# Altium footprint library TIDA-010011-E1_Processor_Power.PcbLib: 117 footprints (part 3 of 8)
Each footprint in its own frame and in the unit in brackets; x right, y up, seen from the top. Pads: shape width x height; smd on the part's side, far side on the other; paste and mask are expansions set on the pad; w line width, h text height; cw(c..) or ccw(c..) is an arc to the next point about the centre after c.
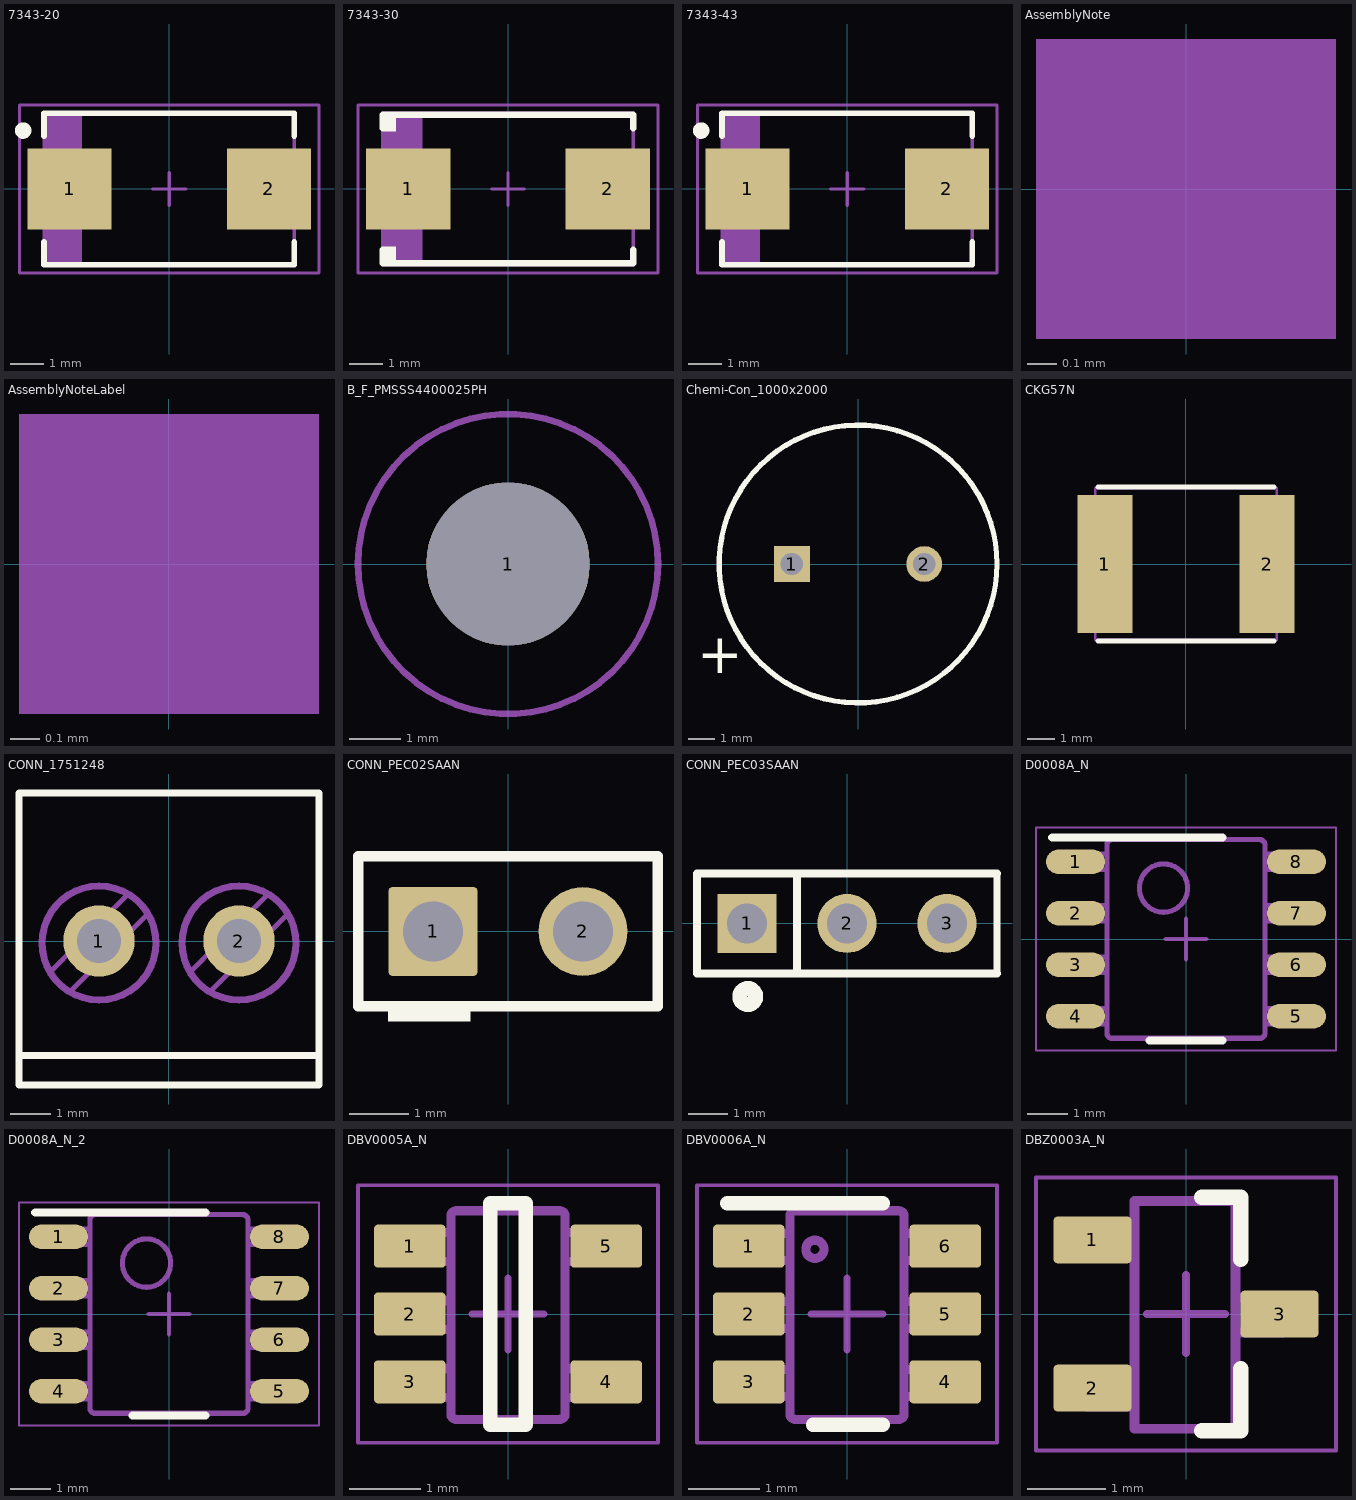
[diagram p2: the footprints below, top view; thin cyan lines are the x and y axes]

## 7343-20 [mm] "Medium density IPC, based on Kemet case V from T495 datasheet"
height 2
pads (2):
  rect 2.55x2.45 smd: 1(-3.025,0) 2(3.025,0)
Top Overlay:
  circle w0.25: c-4.439,1.775 r0.125
  lines w0.178: -3.8,-1.614 -3.8,-2.3 3.8,-2.3 3.8,-1.614 ; -3.8,1.614 -3.8,2.3 3.8,2.3 3.8,1.614
Mechanical 5:
  rectangle: -3.8,-2.3 -2.7,2.3
  lines w0.1: -2.7,-2.3 -2.7,2.3 ; -3.8,-2.3 3.8,-2.3 3.8,2.3 -3.8,2.3 -3.8,-2.3
  text ".Designator" at 0.343,-0.806 h0.51
Mechanical 15:
  lines w0.1: -0.5,0 0.5,0 ; 0,-0.5 0,0.5 ; -4.55,-2.55 -4.55,2.55 4.55,2.55 4.55,-2.55 -4.55,-2.55
3D body: height 2, standoff 0, extent -3.8,-2.3 3.8,2.3
3D body: height 2, standoff 2, extent -3.799,-2.299 -2.701,2.299

## 7343-30 [mm] "Medium Density based on Kemet T495 dimensions"
height 3
pads (2):
  rect 2.55x2.45 smd: 1(-3.025,0) 2(3.025,0)
Top Overlay:
  rectangle: -3.8,1.75 -3.4,2.25
  rectangle: -3.8,-2.25 -3.4,-1.75
  lines w0.2: -3.8,-1.85 -3.8,-2.25 3.8,-2.25 3.8,-1.85 ; -3.8,1.85 -3.8,2.25 3.8,2.25 3.8,1.85
Mechanical 5:
  rectangle: -3.8,-2.3 -2.65,2.3
  lines w0.1: -2.65,-2.3 -2.65,2.3 ; -3.8,-2.3 3.8,-2.3 3.8,2.3 -3.8,2.3 -3.8,-2.3
  text ".Designator" at 0.038,0.679 h0.51
Mechanical 15:
  lines w0.1: -0.5,0 0.5,0 ; 0,-0.5 0,0.5 ; -4.55,-2.55 -4.55,2.55 4.55,2.55 4.55,-2.55 -4.55,-2.55
3D body: height 3, standoff 0, extent -3.8,-2.3 3.8,2.3
3D body: height 3.1, standoff 3.01, extent -3.799,-2.299 -2.651,2.299

## 7343-43 [mm] "Medium density IPC based on Kemet T495 series"
height 4.3
pads (2):
  rect 2.55x2.45 smd: 1(-3.025,0) 2(3.025,0)
Top Overlay:
  circle w0.25: c-4.439,1.775 r0.125
  lines w0.178: -3.8,-1.614 -3.8,-2.3 3.8,-2.3 3.8,-1.614 ; -3.8,1.614 -3.8,2.3 3.8,2.3 3.8,1.614
Mechanical 5:
  rectangle: -3.8,-2.3 -2.7,2.3
  lines w0.1: -2.7,-2.3 -2.7,2.3 ; -3.8,-2.3 3.8,-2.3 3.8,2.3 -3.8,2.3 -3.8,-2.3
  text ".Designator" at 0.404,-0.45 h0.51
Mechanical 15:
  lines w0.1: -0.5,0 0.5,0 ; 0,-0.5 0,0.5 ; -4.55,-2.55 4.55,-2.55 4.55,2.55 -4.55,2.55 -4.55,-2.55
3D body: height 4.3, standoff 0, extent -3.8,-2.3 3.8,2.3
3D body: height 4.3, standoff 4.3, extent -3.799,-2.299 -2.701,2.299

## AssemblyNote [mm] "Assembly Note"
Mechanical 5:
  rectangle: -0.508,-0.508 0.508,0.508
  text ".Comment" at 1.143,-0.508 h0.51
  text ".Designator" at -4.191,-0.508 h0.51

## AssemblyNoteLabel [mm] "Assembly Note for PCB Labels"
Mechanical 5:
  rectangle: -0.508,-0.508 0.508,0.508
  text "Install label in silkscreened box after final wash.  Text shall be 8 pt font.  Text shall be per the Label Table in the PDF schematic." at 1.143,-0.508 h0.51
  text ".Designator" at -4.191,-0.508 h0.51

## B_F_PMSSS4400025PH [mm] "MACHINE SCREW PAN PHILLIPS 4-40"
height 2.1
pads (1):
  round 3.175 hole 3.175 unplated mask+0.127: 1(0,0)
Mechanical 5:
  circle w0.127: c0,0 r2.921
  text ".Designator" at -0.546,-0.121 h0.51
3D body "PMSSS 440 0025 PH.stp": height 2.01, standoff -6.3, extent -2.781,-2.781 2.781,2.781

## Chemi-Con_1000x2000 [mm] "TH, 2-Leads, Body 10x20mm, Pin Spacing 5mm"
height 21.5
pads (2):
  rect 1.35x1.35 hole 0.85: 1(-2.5,0)
  round 1.35 hole 0.85: 2(2.5,0)
Top Overlay:
  circle w0.2: c0,0 r5.25
  text "+" at -6.088,-4.128 h1.5
Mechanical 5:
  lines w0.1: 5.25,-0.001 cw(c0,0) 5.25,0
  text ".Designator" at -0.265,-1.143 h0.51
  text "+" at -3.897,-0.229 h0.51
3D body: height 0, standoff -2, extent 2.203,-0.299 2.8,0.3
3D body: height 0, standoff -2.5, extent -2.797,-0.299 -2.2,0.3
3D body: height 21.5, standoff 0, extent -4.25,-4.25 4.249,4.249
3D body: height 21.5, standoff 0, extent 3.68,-2.626 5.25,2.622
3D body: height 21.5, standoff 0, extent -5.249,-5.25 4.55,5.25

## CKG57N [mm] "Chip Capacitor, Body 6.0x5.0x5.0mm,"
height 5.5
pads (2):
  rect 2x5 smd: 1(-2.95,0) 2(2.95,0)
Top Overlay:
  lines w0.18: -3.2,-2.8 3.2,-2.8 ; -3.2,2.8 3.2,2.8
Mechanical 5:
  lines w0.1: -3.3,-2.75 3.3,-2.75 3.3,2.75 -3.3,2.75 -3.3,-2.75
  text ".Designator" at 0.227,-0.628 h0.51
3D body: height 1, standoff 0, extent 3.101,-2.749 3.299,2.749
3D body: height 1, standoff 0, extent -3.299,-2.749 -3.101,2.749
3D body: height 5.5, standoff 1, extent -2.199,-2.749 2.199,2.749
3D body: height 5.5, standoff 1, extent 2.201,-2.749 3.299,2.749
3D body: height 5.5, standoff 1, extent -3.299,-2.749 -2.201,2.749
3D body: height 0.3, standoff 0, extent -3.299,-2.749 -1.701,2.749
3D body: height 0.3, standoff 0, extent 1.701,-2.749 3.299,2.749
3D body: height 5.5, standoff 1, extent -3.299,-2.749 -3.101,2.749

## CONN_1751248 [mm] "Phoenix Contact"
height 8.5
pads (2):
  round 1.778 hole 1.1: 1(-1.75,0) 2(1.75,0)
Top Overlay:
  lines w0.178: -3.75,-2.861 3.75,-2.861 ; -3.75,-2.861 -3.75,-3.3 -3.75,-3.6 3.75,-3.6 3.75,-3.3 3.75,-2.861 ; -3.75,-2.861 -3.75,-2.049 -3.75,-1.566 -3.75,1.487 -3.75,1.962 -3.75,3.7 3.75,3.7 3.75,1.962 3.75,1.487 3.75,-1.566 3.75,-2.049 3.75,-2.861
Mechanical 5:
  lines w0.127: -3.75,-2.861 -3.75,-2.049 -3.75,-1.566 -3.75,1.487 -3.75,1.962 -3.75,3.7 3.75,3.7 3.75,1.962 3.75,1.487 3.75,-1.566 3.75,-2.049 3.75,-2.861 ; -3.75,-2.861 -3.75,-3.3 -3.75,-3.6 3.75,-3.6 3.75,-3.3 3.75,-2.861 ; -3.75,-2.861 3.75,-2.861 ; -2.956,-0.761 ccw(c-1.75,-0.05) -2.461,-1.256 ; -2.956,-0.761 cw(c-1.75,-0.05) -1.75,1.35 cw(c-1.75,-0.05) -1.039,1.156 ; -2.956,-0.761 -2.291,-0.096 -1.75,0.445 -1.653,0.542 -1.039,1.156 ; -2.461,-1.256 ccw(c-1.75,-0.05) -1.75,-1.45 ccw(c-1.75,-0.05) -0.544,0.661 ; -2.461,-1.256 -1.755,-0.55 -1.75,-0.545 -1.2,0.005 -0.544,0.661 ; -1.039,1.156 cw(c-1.75,-0.05) -0.544,0.661 ; 0.544,-0.761 cw(c1.75,-0.05) 1.75,1.35 cw(c1.75,-0.05) 2.461,1.156 ; 0.544,-0.761 ccw(c1.75,-0.05) 1.039,-1.256 ; 0.544,-0.761 1.209,-0.096 1.75,0.445 1.847,0.542 2.461,1.156 ; 1.039,-1.256 ccw(c1.75,-0.05) 1.75,-1.45 ccw(c1.75,-0.05) 2.956,0.661 ; 1.039,-1.256 1.745,-0.55 1.75,-0.545 2.3,0.005 2.956,0.661 ; 2.461,1.156 cw(c1.75,-0.05) 2.956,0.661 ; -1.75,-1.5 cw(c-1.75,-0.05) -1.75,1.4 cw(c-1.75,-0.05) -1.75,-1.5 ; 1.75,-1.5 cw(c1.75,-0.05) 1.75,1.4 cw(c1.75,-0.05) 1.75,-1.5
  text ".Designator" at -0.381,2.184 h0.51
3D body "Phoenix_1751248.stp": height 8.52, standoff -3.48, extent -3.75,-3.6 3.75,3.7

## CONN_PEC02SAAN [mm] "SULLINS"
height 8.38
pads (2):
  rrect7% 1.5x1.5 hole 1.016: 1(-1.27,0)
  round 1.5 hole 1.016: 2(1.27,0)
Top Overlay:
  rectangle: -2.032,-1.524 -0.635,-1.27
  lines w0.178: -2.54,-1.27 -2.54,1.27 2.54,1.27 2.54,-1.27 -2.54,-1.27
Mechanical 5:
  lines w0.127: -2.54,-1.27 2.54,-1.27 2.54,1.27 -2.54,1.27 -2.54,-1.27
  text ".Designator" at -0.559,-0.229 h0.51
3D body: height 2.54, standoff 0, extent -2.539,-1.269 2.539,1.269
3D body: height 8.38, standoff -3.05, extent -1.574,-0.304 -0.966,0.304
3D body: height 8.38, standoff -3.05, extent 0.966,-0.304 1.574,0.304

## CONN_PEC03SAAN [mm] "SULLINS"
height 8.38
pads (3):
  rect 1.5x1.5 hole 1.016: 1(-2.54,0)
  round 1.5 hole 1.016: 2(0,0) 3(2.54,0)
Top Overlay:
  circle w0.381: c-2.521,-1.856 r0.203
  lines w0.178: 3.81,-1.27 3.81,0.254 3.81,1.27
  lines w0.203: -1.27,1.27 -1.27,-1.27 ; 3.81,-1.27 -1.27,-1.27 ; 3.81,1.27 -3.81,1.27 -3.81,-1.27 -1.27,-1.27
Mechanical 5:
  rectangle: -3.048,-0.508 -2.032,0.508
  lines w0.127: -3.81,-1.27 -3.81,1.27 3.81,1.27 3.81,-1.27 -3.81,-1.27
  text ".Designator" at 0.933,0.125 h0.51
3D body: height 8.38, standoff -3.05, extent 2.236,-0.304 2.844,0.304
3D body: height 8.38, standoff -3.05, extent -0.304,-0.304 0.304,0.304
3D body: height 8.38, standoff -3.05, extent -2.844,-0.304 -2.236,0.304
3D body: height 2.54, standoff 0, extent -3.835,-1.295 3.835,1.295

## D0008A_N [mm] "SOIC, 8-Leads, Body 4.9x3.9mm, Pitch 1.27mm, IPC Medium Density"
height 1.75
pads (8):
  oval 1.45x0.6 smd: 1(-2.725,1.905) 2(-2.725,0.635) 3(-2.725,-0.635) 4(-2.725,-1.905) 5(2.725,-1.905) 6(2.725,-0.635) 7(2.725,0.635) 8(2.725,1.905)
Top Overlay:
  lines w0.2: -3.3,2.5 0.9,2.5 ; -0.9,-2.5 0.9,-2.5
Mechanical 5:
  lines w0.127: -2.375,-2.095 -1.995,-2.095 -1.952,-2.095 -1.952,-1.715 -1.995,-1.715 -2.375,-1.715 ; -2.375,-2.095 -2.589,-2.095 -3.002,-2.095 -3.002,-1.715 -2.589,-1.715 -2.375,-1.715 ; -2.375,-2.095 -2.375,-1.715 ; -2.375,-0.825 -1.995,-0.825 -1.952,-0.825 -1.952,-0.445 -1.995,-0.445 -2.375,-0.445 ; -2.375,-0.825 -2.589,-0.825 -3.002,-0.825 -3.002,-0.445 -2.589,-0.445 -2.375,-0.445 ; -2.375,-0.825 -2.375,-0.445 ; -2.375,0.445 -1.995,0.445 -1.952,0.445 -1.952,0.825 -1.995,0.825 -2.375,0.825 ; -2.375,0.445 -2.589,0.445 -3.002,0.445 -3.002,0.825 -2.589,0.825 -2.375,0.825 ; -2.375,0.445 -2.375,0.825 ; -2.375,1.715 -1.995,1.715 -1.952,1.715 -1.952,2.095 -1.995,2.095 -2.375,2.095 ; -2.375,1.715 -2.589,1.715 -3.002,1.715 -3.002,2.095 -2.589,2.095 -2.375,2.095 ; -2.375,1.715 -2.375,2.095 ; -0.332,-2.45 -1.825,-2.45 -1.826,-2.45 cw(c-1.825,-2.323) -1.952,-2.324 -1.952,-2.323 -1.952,2.323 -1.952,2.324 cw(c-1.825,2.323) -1.826,2.45 -1.825,2.45 -0.332,2.45 ; -0.332,-2.45 -0.182,-2.45 ; -0.332,-2.45 -0.182,-2.45 ; -0.332,2.45 -0.182,2.45 ; -0.332,2.45 -0.182,2.45 ; -0.182,-2.45 0.178,-2.45 ; -0.182,2.45 0.178,2.45 ; 0.178,-2.45 0.328,-2.45 ; 0.178,-2.45 0.328,-2.45 ; 0.178,2.45 0.328,2.45 ; 0.178,2.45 0.328,2.45 ; 0.328,-2.45 1.821,-2.45 1.822,-2.45 ccw(c1.821,-2.323) 1.948,-2.324 1.948,-2.323 1.948,2.323 1.948,2.324 ccw(c1.821,2.323) 1.822,2.45 1.821,2.45 0.328,2.45 ; 2.371,-2.095 2.585,-2.095 2.998,-2.095 2.998,-1.715 2.585,-1.715 2.371,-1.715 ; 2.371,-2.095 1.991,-2.095 1.948,-2.095 1.948,-1.715 1.991,-1.715 2.371,-1.715 ; 2.371,-2.095 2.371,-1.715 ; 2.371,-0.825 2.585,-0.825 2.998,-0.825 2.998,-0.445 2.585,-0.445 2.371,-0.445 ; 2.371,-0.825 1.991,-0.825 1.948,-0.825 1.948,-0.445 1.991,-0.445 2.371,-0.445 ; 2.371,-0.825 2.371,-0.445 ; 2.371,0.445 2.585,0.445 2.998,0.445 2.998,0.825 2.585,0.825 2.371,0.825 ; 2.371,0.445 1.991,0.445 1.948,0.445 1.948,0.825 1.991,0.825 2.371,0.825 ; 2.371,0.445 2.371,0.825 ; 2.371,1.715 2.585,1.715 2.998,1.715 2.998,2.095 2.585,2.095 2.371,2.095 ; 2.371,1.715 1.991,1.715 1.948,1.715 1.948,2.095 1.991,2.095 2.371,2.095 ; 2.371,1.715 2.371,2.095 ; -0.555,0.659 cw(c-0.555,1.256) -0.555,1.853 cw(c-0.555,1.256) -0.555,0.659
  text ".Designator" at 0.884,-0.293 h0.51
Mechanical 15:
  lines w0.05: -3.7,-2.75 3.7,-2.75 3.7,2.75 -3.7,2.75 -3.7,-2.75
  lines w0.1: -0.5,0 0.5,0 ; 0,-0.5 0,0.5
3D body "D0008A.stp": height 1.63, standoff 0, extent -3,-2.45 3,2.45

## D0008A_N_2 [mm]
pads (8):
  oval 1.45x0.6 smd: 1(-2.725,1.905) 2(-2.725,0.635) 3(-2.725,-0.635) 4(-2.725,-1.905) 5(2.725,-1.905) 6(2.725,-0.635) 7(2.725,0.635) 8(2.725,1.905)
Top Overlay:
  lines w0.2: -3.3,2.5 0.9,2.5 ; -0.9,-2.5 0.9,-2.5
Mechanical 5:
  lines w0.127: -2.375,-2.095 -1.995,-2.095 -1.952,-2.095 -1.952,-1.715 -1.995,-1.715 -2.375,-1.715 ; -2.375,-2.095 -2.589,-2.095 -3.002,-2.095 -3.002,-1.715 -2.589,-1.715 -2.375,-1.715 ; -2.375,-2.095 -2.375,-1.715 ; -2.375,-0.825 -1.995,-0.825 -1.952,-0.825 -1.952,-0.445 -1.995,-0.445 -2.375,-0.445 ; -2.375,-0.825 -2.589,-0.825 -3.002,-0.825 -3.002,-0.445 -2.589,-0.445 -2.375,-0.445 ; -2.375,-0.825 -2.375,-0.445 ; -2.375,0.445 -1.995,0.445 -1.952,0.445 -1.952,0.825 -1.995,0.825 -2.375,0.825 ; -2.375,0.445 -2.589,0.445 -3.002,0.445 -3.002,0.825 -2.589,0.825 -2.375,0.825 ; -2.375,0.445 -2.375,0.825 ; -2.375,1.715 -1.995,1.715 -1.952,1.715 -1.952,2.095 -1.995,2.095 -2.375,2.095 ; -2.375,1.715 -2.589,1.715 -3.002,1.715 -3.002,2.095 -2.589,2.095 -2.375,2.095 ; -2.375,1.715 -2.375,2.095 ; -0.332,-2.45 -1.825,-2.45 -1.826,-2.45 cw(c-1.825,-2.323) -1.952,-2.324 -1.952,-2.323 -1.952,2.323 -1.952,2.324 cw(c-1.825,2.323) -1.826,2.45 -1.825,2.45 -0.332,2.45 ; -0.332,-2.45 -0.182,-2.45 ; -0.332,-2.45 -0.182,-2.45 ; -0.332,2.45 -0.182,2.45 ; -0.332,2.45 -0.182,2.45 ; -0.182,-2.45 0.178,-2.45 ; -0.182,2.45 0.178,2.45 ; 0.178,-2.45 0.328,-2.45 ; 0.178,-2.45 0.328,-2.45 ; 0.178,2.45 0.328,2.45 ; 0.178,2.45 0.328,2.45 ; 0.328,-2.45 1.821,-2.45 1.822,-2.45 ccw(c1.821,-2.323) 1.948,-2.324 1.948,-2.323 1.948,2.323 1.948,2.324 ccw(c1.821,2.323) 1.822,2.45 1.821,2.45 0.328,2.45 ; 2.371,-2.095 2.585,-2.095 2.998,-2.095 2.998,-1.715 2.585,-1.715 2.371,-1.715 ; 2.371,-2.095 1.991,-2.095 1.948,-2.095 1.948,-1.715 1.991,-1.715 2.371,-1.715 ; 2.371,-2.095 2.371,-1.715 ; 2.371,-0.825 2.585,-0.825 2.998,-0.825 2.998,-0.445 2.585,-0.445 2.371,-0.445 ; 2.371,-0.825 1.991,-0.825 1.948,-0.825 1.948,-0.445 1.991,-0.445 2.371,-0.445 ; 2.371,-0.825 2.371,-0.445 ; 2.371,0.445 2.585,0.445 2.998,0.445 2.998,0.825 2.585,0.825 2.371,0.825 ; 2.371,0.445 1.991,0.445 1.948,0.445 1.948,0.825 1.991,0.825 2.371,0.825 ; 2.371,0.445 2.371,0.825 ; 2.371,1.715 2.585,1.715 2.998,1.715 2.998,2.095 2.585,2.095 2.371,2.095 ; 2.371,1.715 1.991,1.715 1.948,1.715 1.948,2.095 1.991,2.095 2.371,2.095 ; 2.371,1.715 2.371,2.095 ; -0.555,0.659 cw(c-0.555,1.256) -0.555,1.853 cw(c-0.555,1.256) -0.555,0.659
  text ".Designator" at 0.813,-0.508 h0.51
Mechanical 15:
  lines w0.05: -3.7,-2.75 3.7,-2.75 3.7,2.75 -3.7,2.75 -3.7,-2.75
  lines w0.1: -0.5,0 0.5,0 ; 0,-0.5 0,0.5
3D body "D0008A.stp": height 1.63, standoff 0, extent -3,-2.45 3,2.45

## DBV0005A_N [mm] "SOT23, 5-Leads, Body 2.9x1.6mm, Pitch 0.95mm, Lead Span 2.8mm, IPC Medium Density"
height 1.45
pads (5):
  rrect17% 1x0.6 smd: 1(-1.375,0.95) 2(-1.375,0) 3(-1.375,-0.95) 4(1.375,-0.95) 5(1.375,0.95)
Top Overlay:
  lines w0.2: -0.25,-1.55 -0.25,1.55 0.25,1.55 0.25,-1.55 -0.25,-1.55
Mechanical 5:
  lines w0.127: -0.801,1.371 cw(c-0.725,1.37) -0.725,1.446 ; -0.801,1.37 -0.801,1.371 ; -0.801,1.37 -0.801,-1.399 -0.801,-1.4 ccw(c-0.725,-1.399) -0.725,-1.475 ; -0.725,-1.475 0.723,-1.475 0.724,-1.475 ccw(c0.723,-1.399) 0.799,-1.4 0.799,-1.399 0.799,1.37 ; -0.725,-1.475 -0.725,-1.475 ; -0.725,1.446 -0.725,1.446 ; -0.725,1.446 0.723,1.446 0.724,1.446 cw(c0.723,1.37) 0.799,1.371 ; 0.799,1.37 0.799,1.371 ; -1.423,-1.167 -1.423,-0.767 -1.199,-0.767 -1.105,-0.767 -1.088,-0.767 -0.835,-0.767 -0.801,-0.767 -0.801,-1.167 -0.835,-1.167 -1.088,-1.167 -1.105,-1.167 -1.199,-1.167 -1.423,-1.167 ; -1.423,-0.215 -1.423,0.186 -1.199,0.186 -1.105,0.186 -1.088,0.186 -0.835,0.186 -0.801,0.186 -0.801,-0.215 -0.835,-0.215 -1.088,-0.215 -1.105,-0.215 -1.199,-0.215 -1.423,-0.215 ; -1.423,0.738 -1.423,1.138 -1.199,1.138 -1.105,1.138 -1.088,1.138 -0.835,1.138 -0.801,1.138 -0.801,0.738 -0.835,0.738 -1.088,0.738 -1.105,0.738 -1.199,0.738 -1.423,0.738 ; 0.799,-1.167 0.834,-1.167 1.087,-1.167 1.103,-1.167 1.198,-1.167 1.422,-1.167 1.422,-0.767 1.198,-0.767 1.103,-0.767 1.087,-0.767 0.834,-0.767 0.799,-0.767 0.799,-1.167 ; 0.799,0.738 0.834,0.738 1.087,0.738 1.103,0.738 1.198,0.738 1.422,0.738 1.422,1.138 1.198,1.138 1.103,1.138 1.087,1.138 0.834,1.138 0.799,1.138 0.799,0.738
  text ".Designator" at -0.25,0.95 h0.51
Mechanical 15:
  lines w0.05: -2.1,-1.8 -2.1,1.8 2.1,1.8 2.1,-1.8 -2.1,-1.8
  lines w0.1: -0.5,0 0.5,0 ; 0,-0.5 0,0.5
3D body "DBV0005A.stp": height 1.09, standoff 0, extent -1.422,-1.461 1.423,1.46

## DBV0006A_N [mm] "SOT23, 6-Leads, Body 2.9x1.6mm, Pitch 0.95mm, Lead Span 2.8mm, IPC Medium Density"
height 1.45
pads (6):
  rrect17% 1x0.6 smd: 1(-1.375,0.95) 2(-1.375,0) 3(-1.375,-0.95) 4(1.375,-0.95) 5(1.375,0) 6(1.375,0.95)
Top Overlay:
  lines w0.2: -1.675,1.55 0.5,1.55 ; -0.475,-1.55 0.5,-1.55
Mechanical 5:
  lines w0.127: 0.724,-1.475 ccw(c0.723,-1.399) 0.8,-1.399 0.8,1.37 ccw(c0.723,1.37) 0.724,1.446 ; 0.723,-1.475 0.724,-1.475 ; 0.723,-1.475 -0.724,-1.475 -0.725,-1.475 cw(c-0.724,-1.399) -0.801,-1.399 -0.801,1.37 cw(c-0.724,1.37) -0.725,1.446 -0.724,1.446 0.723,1.446 ; 0.723,1.446 0.724,1.446 ; -1.423,-1.154 -1.206,-1.154 -1.113,-1.154 -1.081,-1.154 -0.828,-1.154 -0.801,-1.154 -0.801,-0.78 -0.828,-0.78 -1.081,-0.78 -1.113,-0.78 -1.206,-0.78 -1.423,-0.78 -1.423,-1.154 ; -1.423,-0.202 -1.206,-0.202 -1.113,-0.202 -1.081,-0.202 -0.828,-0.202 -0.801,-0.202 -0.801,0.173 -0.828,0.173 -1.081,0.173 -1.113,0.173 -1.206,0.173 -1.423,0.173 -1.423,-0.202 ; -1.423,0.751 -1.206,0.751 -1.113,0.751 -1.081,0.751 -0.828,0.751 -0.801,0.751 -0.801,1.125 -0.828,1.125 -1.081,1.125 -1.113,1.125 -1.206,1.125 -1.423,1.125 -1.423,0.751 ; -0.577,0.906 cw(c-0.45,0.906) -0.323,0.906 cw(c-0.45,0.906) -0.577,0.906 ; 0.8,-1.154 0.827,-1.154 1.08,-1.154 1.112,-1.154 1.205,-1.154 1.422,-1.154 1.422,-0.78 1.205,-0.78 1.112,-0.78 1.08,-0.78 0.827,-0.78 0.8,-0.78 0.8,-1.154 ; 0.8,-0.202 0.827,-0.202 1.08,-0.202 1.112,-0.202 1.205,-0.202 1.422,-0.202 1.422,0.173 1.205,0.173 1.112,0.173 1.08,0.173 0.827,0.173 0.8,0.173 0.8,-0.202 ; 0.8,0.751 0.827,0.751 1.08,0.751 1.112,0.751 1.205,0.751 1.422,0.751 1.422,1.125 1.205,1.125 1.112,1.125 1.08,1.125 0.827,1.125 0.8,1.125 0.8,0.751
  text ".Designator" at -0.127,0.432 h0.51
Mechanical 15:
  lines w0.05: -2.1,-1.8 2.1,-1.8 2.1,1.8 -2.1,1.8 -2.1,-1.8
  lines w0.1: -0.5,0 0.5,0 ; 0,-0.5 0,0.5
3D body "DBV0006A.stp": height 1.12, standoff 0, extent -1.422,-1.461 1.423,1.46

## DBZ0003A_N [mm] "SOT23, 3-Leads, Body 2.9x1.3mm, Pitch 0.95mm, Lead Span 2.4mm, IPC Medium Density"
height 1.12
pads (3):
  rrect17% 1x0.6 smd: 1(-1.2,0.95) 2(-1.2,-0.95) 3(1.2,0)
Top Overlay:
  lines w0.2: 0.2,-1.5 0.7,-1.5 0.7,-0.7 ; 0.2,1.5 0.7,1.5 0.7,0.7
Mechanical 5:
  lines w0.127: -1.27,-1.187 -1.063,-1.187 -1.005,-1.187 -0.814,-1.187 -0.66,-1.187 -0.66,-0.743 -0.814,-0.743 -1.005,-0.743 -1.063,-0.743 -1.27,-0.743 -1.27,-1.187 ; -1.27,0.718 -1.063,0.718 -1.005,0.718 -0.814,0.718 -0.66,0.718 -0.66,1.162 -0.814,1.162 -1.005,1.162 -1.063,1.162 -1.27,1.162 -1.27,0.718 ; -0.66,-1.473 0.635,-1.473 0.635,1.448 -0.66,1.448 -0.66,-1.473 ; 0.635,-0.235 0.635,0.21 0.789,0.21 0.98,0.21 1.037,0.21 1.245,0.21 1.245,-0.235 1.037,-0.235 0.98,-0.235 0.789,-0.235 0.635,-0.235
  text ".Designator" at -0.254,0.889 h0.51
Mechanical 15:
  lines w0.05: -1.925,-1.75 -1.925,1.75 1.925,1.75 1.925,-1.75 -1.925,-1.75
  lines w0.1: -0.5,0 0.5,0 ; 0,-0.5 0,0.5
3D body "DBZ0003A.stp": height 0.98, standoff 0, extent -1.257,-1.461 1.258,1.461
